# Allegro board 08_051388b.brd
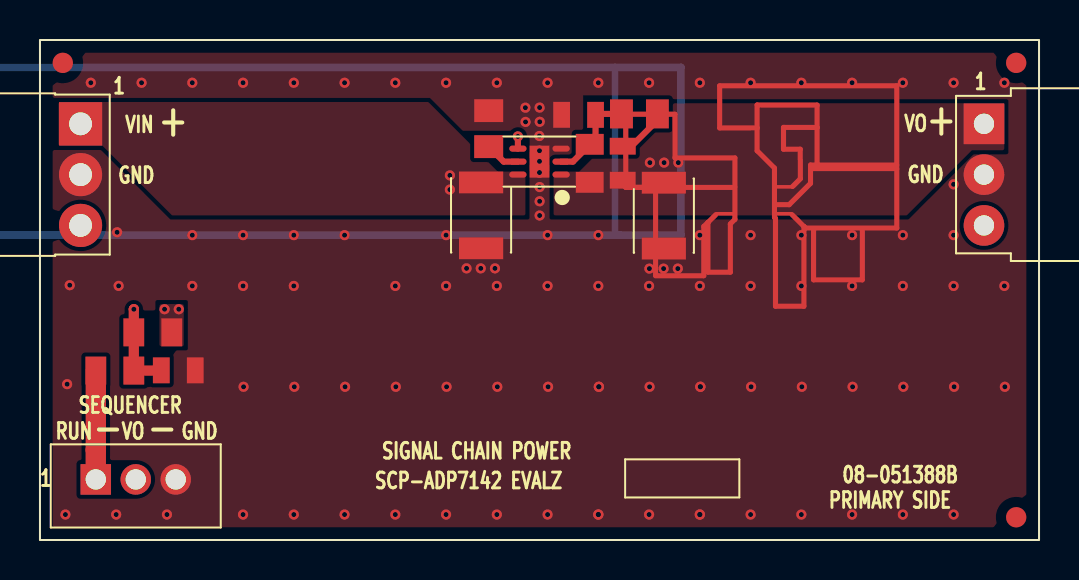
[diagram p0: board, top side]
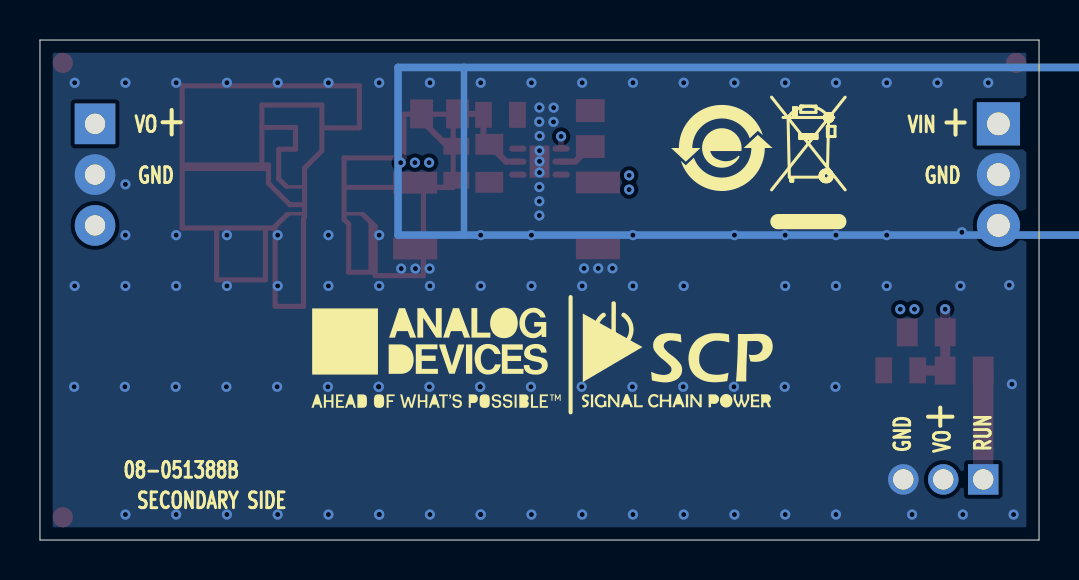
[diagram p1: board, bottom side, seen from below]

Outline 50 x 25 mm; copper layers: TOP, L2_GND, L3_SIG, BOTTOM. Coordinates in mm from the lower left corner of the outline.
Outline path: 0,25 50,25 50,0 0,0 0,25

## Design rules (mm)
constraint set DEFAULT: min track width 0.203

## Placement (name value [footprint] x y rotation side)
C1  2.2uF  [C1210H87]  22.08 16.23 270 top
C2  2.2uF  [C1210H87]  31.22 16.22 270 top
C3  1000PF  [C0805]  22.46 20.57 90 top
C4  0.1uF  [C0805]  30 21.31 180 top
INPUT  PBC03SBAN  [CNTHMHDRRA1X3L300W100H145]  2.03 20.81 270 top
NOREF  -  []  50.02 -0.07 90 top
NOREF#2  -  []  -0.02 25.07 270 top
NOREF#3  -  []  0 25 0 top
NOREF#4  -  []  2.03 20.81 0 top
NOREF#5  -  []  50 0 0 top
NOREF#6  -  []  -36.32 105.77 0 top
NOREF#7  -  []  -19.05 286.11 0 top
NOREF#8  -  [unnamed#2]  48.86 1.14 0 top
NOREF#9  -  []  0 0 0 top
NOREF#10  -  [unnamed#2]  1.14 23.86 0 top
NOREF#11  -  []  -69.98 -54.12 0 top
NOREF#12  -  []  -0.02 -0.07 0 top
NOREF#13  -  [unnamed#2]  48.86 23.86 0 top
NOREF#14  -  []  50 0 90 top
NOREF#15  -  []  50.02 25.07 180 top
NOREF#16  -  []  25.1 39.22 0 top
NOREF#17  -  []  0 0 0 top
NOREF#18  -  []  0 25 0 top
NOREF#19  -  []  92.2 43.03 0 top
NOREF#20  -  []  2.03 20.81 0 top
NOREF#21  -  []  -59.69 348.22 0 top
NOREF#22  -  []  15.88 19.6 180 bottom
NOREF#23  -  []  11.74 15.6 180 bottom
NOREF#24  -  []  30.47 9.07 180 bottom
NOREF#25  -  []  18.07 9.28 180 bottom
OUTPUT  PPPC031LGBN-RC  [CNHDRRA1X3H108]  47.24 20.81 270 top
P1  53253-0370  [CNTHMHDR1X3L315W144H224]  2.79 3.03 0 top
R1  187K  [R0805#2]  27.51 18.83 90 top
R2  10K  [R0805]  26.96 21.26 180 top
R3  1K  [R0805]  29.16 18.84 90 top
R4  1MEG  [R0805#2]  5.64 10.38 180 top
R5  TBD0805  [R0805#2]  3.75 8.47 0 top
R6  TBD0805  [R0805]  6.92 8.48 0 top
U1  ADP7142ACPZN  [DFN6_2X2_PAD1_6X1]  25 18.92 90 top

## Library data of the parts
C1 C2 = CAP: Tolerance: 10; User Part Number: UPN; alternate symbols: (); part number: CAP_SM-2.2UF,100V,10,E015185,C1210H87; tolerance: 10
C3 = CAP: User Part Number: UPN; Tolerance: 10; alternate symbols: (); part number: CAP_SM-1000PF,100V,10,E026082,C0805; tolerance: 10
C4 = CAP: User Part Number: UPN; Tolerance: 5; alternate symbols: (); part number: CAP_SM-0.1UF,50V,5,E015576,C0805; tolerance: 5
INPUT = CN3P: Tolerance: N/A; User Part Number: UPN; alternate symbols: (CNTHMHDRRA1X3L300W100H145_SCP); part number: CN3P_TH-PBC03SBAN,E034137,CNTHMHDRRA1X3L300W100H145; tolerance: N/A
OUTPUT = CN3P: User Part Number: UPN; Tolerance: N/A; alternate symbols: (CNHDRRA1X3H108_SCP); part number: CN3P_TH-PPPC031LGBN-RC,E034111,CNHDRRA1X3H108; tolerance: N/A
P1 = CN3P: Tolerance: N/A; User Part Number: UPN; alternate symbols: (); part number: CN3P_TH-53253-0370,E033940,CNTHMHDR1X3L315W144H224; tolerance: N/A
R1 = RES: User Part Number: UPN; Tolerance: 1; alternate symbols: (R0805L); part number: RES_SM-187K,E015129,1/8W,1,R0805; tolerance: 1
R2 = RES: User Part Number: UPN; Tolerance: 1; alternate symbols: (R0805L); part number: RES_SM-10K,E023450,1/3W,1,R0805; tolerance: 1
R3 = RES: User Part Number: UPN; Tolerance: 1; alternate symbols: (R0805L); part number: RES_SM-1K,E023448,1/3W,1,R0805; tolerance: 1
R4 = RES: User Part Number: UPN; Tolerance: 5; alternate symbols: (); part number: RES_SM-1MEG,E033749,1/8W,5,R0805; tolerance: 5
R5 R6 = RES: User Part Number: UPN; alternate symbols: (R0805L); part number: RES_SM-TBD0805,E004051,TBD0805,TBD0805,R0805
U1 = ADP7142: User Part Number: UPN; Tolerance: N/A; alternate symbols: (); part number: ADP7142_SM-ADP7142ACPZN-R7,E017499,DFN6_2X2_PAD1_6X1; tolerance: N/A

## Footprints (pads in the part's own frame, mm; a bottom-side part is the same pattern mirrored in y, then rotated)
C0805
  rect 1.143x1.448 smd: 1(-0.9,0) 2(0.9,0)
C1210H87
  rect 1.092x2.21 smd: 1(-1.646,0) 2(1.646,0)
CNHDRRA1X3H108
  rect 2.032x2.032 hole 1.016: 1(0,0)
  round 2.032 hole 1.016: 2(2.54,0) 3(5.08,0)
CNTHMHDR1X3L315W144H224
  rect 1.524x1.524 hole 1.016: 1(0,0)
  round 1.524 hole 1.016: 2(2,0) 3(4,0)
CNTHMHDRRA1X3L300W100H145
  rect 2.159x2.159 hole 1.143: 1(0,0)
  round 2.159 hole 1.143: 2(2.54,0) 3(5.08,0)
DFN6_2X2_PAD1_6X1
  oval 0.305x0.864 smd: 1(-0.65,-1.082) 2(0,-1.082) 3(0.65,-1.082) 4(0.65,1.082) 5(0,1.082) 6(-0.65,1.082)
  rect 1.6x0.991 smd: PAD(0,0)
R0805
  rect 0.838x1.295 smd: 1(-0.85,0) 2(0.85,0)
R0805#2
  rect 1.041x1.397 smd: 1(-0.95,0) 2(0.95,0)
unnamed#2
  round 1.016 smd: (0,0)

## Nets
GND: C1.2(N2) C2.2(N2) C3.2(N2) INPUT.2 OUTPUT.2 P1.3(N3) R2.2(N2) R6.2(N2) U1.3 U1.PAD
VIN+: C1.1 INPUT.1 R4.1 U1.6
RUN: P1.1 R5.1
UNNAMED_2_ADP7142_I1_EN: R4.2(N2) R5.2(N2) R6.1 U1.4
UNNAMED_2_ADP7142_I1_SENSE: C4.2(N2) R1.2(N2) R2.1 U1.2
UNNAMED_2_ADP7142_I1_SS: C3.1 U1.5
UNNAMED_2_CAP_I7_N1: C4.1 R3.2(N2)
VO+: C2.1 OUTPUT.1 P1.2 R1.1 R3.1 U1.1(VOUT)

Pads without a net: INPUT 3; OUTPUT 3

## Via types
v1: diameter 0.508, hole 0.254, TOP to BOTTOM, 117 vias

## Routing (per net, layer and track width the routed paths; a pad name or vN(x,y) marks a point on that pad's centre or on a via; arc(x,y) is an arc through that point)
GND: length 0
  vias: v1(1.27,1.27) v1(1.36,7.79) v1(1.49,12.74) v1(2.54,22.86) v1(3.86,15.39) v1(3.81,1.27) v1(3.94,12.71) v1(5.08,22.86) v1(6.35,1.27) v1(7.62,22.86) v1(7.62,15.24) v1(7.62,12.7) v1(10.16,22.86) v1(10.16,15.24) v1(10.16,12.7) v1(10.16,1.27) v1(10.19,7.66) v1(12.7,22.86) v1(12.7,15.24) v1(12.7,12.7) v1(12.73,7.66) v1(12.7,1.27) v1(15.24,22.86) v1(15.24,15.24) v1(15.27,7.66) v1(15.24,1.27) v1(17.78,22.86) v1(17.78,12.7) v1(17.81,7.66) v1(17.78,1.27) v1(20.32,22.86) v1(20.32,15.24) v1(20.32,12.7) v1(20.35,7.66) v1(20.32,1.27) v1(21.35,13.58) v1(22.06,13.58) v1(22.77,13.58) v1(22.86,22.86) v1(22.86,12.7) v1(22.86,1.27) v1(22.89,7.66) v1(24.29,21.62) v1(24.3,20.9) v1(25,21.62) v1(25.01,20.91) v1(24.99,20.2) v1(25,19.47) v1(25,18.93) v1(25,18.37) v1(25.01,17.65) v1(25.01,16.94) v1(25.01,16.22) v1(25.4,22.86) v1(25.4,15.24) v1(25.4,12.7) v1(25.43,7.66) v1(25.4,1.27) v1(27.94,22.86) v1(27.94,15.24) v1(27.94,12.7) v1(27.97,7.66) v1(27.97,7.66) v1(27.94,1.27) v1(27.94,1.27) v1(30.48,22.86) v1(30.5,13.57) v1(30.48,12.7) v1(30.51,7.66) v1(30.48,1.27) v1(31.21,13.57) v1(31.92,13.57) v1(33.02,22.86) v1(33.02,15.24) v1(33.02,12.7) v1(33.05,7.66) v1(33.05,7.66) v1(33.02,1.27) v1(33.02,1.27) v1(35.56,22.86) v1(35.56,15.24) v1(35.56,12.7) v1(35.56,1.27) v1(35.59,7.66) v1(38.1,22.86) v1(38.1,15.24) v1(38.1,12.7) v1(38.13,7.66) v1(38.1,1.27) v1(40.64,22.86) v1(40.64,15.24) v1(40.64,12.7) v1(40.67,7.66) v1(40.64,1.27) v1(43.18,22.86) v1(43.18,15.24) v1(43.18,12.7) v1(43.21,7.66) v1(43.18,1.27) v1(45.72,22.86) v1(45.72,17.78) v1(45.72,15.24) v1(45.72,12.7) v1(45.75,7.66) v1(45.72,1.27) v1(48.26,22.86) v1(48.26,12.7) v1(48.29,7.66)
VIN+: length 17.5
  L3_SIG w0.508: v1(20.51,18.23) v1(20.51,17.52) 14.53,11.54 v1(6.95,11.54) v1(6.24,11.54)
RUN: length 5.4
  TOP w1.016: R5.1 2.8,4.5 2.79,4.5 P1.1
UNNAMED_2_ADP7142_I1_EN: length 29.3
  TOP w0.305: U1.4 v1(23.92,20.18)
  TOP w0.508: R6.1 6.06,8.47 R5.2 4.7,10.38 R4.2 4.69,11.53 v1(4.7,11.54)
  L3_SIG w0.508: v1(23.92,20.18) 10.8,20.18 4.7,14.08 v1(4.7,11.54)
UNNAMED_2_ADP7142_I1_SENSE: length 4.7
  TOP w0.305: C4.2 27.85,21.31 R2.1 27.81,20.08 R1.2 27.51,19.76 26.67,18.92 U1.2
UNNAMED_2_ADP7142_I1_SS: length 1.8
  TOP w0.305: C3.1 23.21,18.92 U1.5
UNNAMED_2_CAP_I7_N1: length 2.6
  TOP w0.305: R3.2 29.6,19.69 30.9,20.99 C4.1
VO+: length 34.5
  L3_SIG w0.508: v1(31.95,18.87) v1(31.24,18.87) v1(30.52,18.87) 20.46,8.81 9.28,8.81 4.79,4.32 P1.2

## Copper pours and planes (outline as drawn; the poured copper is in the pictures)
GND on TOP: 0.64,0.64 0.64,24.36 49.36,24.36 49.36,0.64 ; 5 cut-outs
GND on BOTTOM, L2_GND, L3_SIG: 0.64,0.64 0.64,24.36 49.36,24.36 49.36,0.64
VIN+ on TOP: 24.3,18.42 24.3,16.23 6.61,16.23 3.14,19.7 0.93,19.7 0.93,21.9 19.43,21.9 22.91,18.42
VIN+ on TOP: 5.98,9.68 5.98,11.79 7.2,11.79 7.2,9.68
VO+ on TOP: 25.7,16.23 25.7,18.42 26.99,18.42 27.63,19.07 29.81,19.07 29.81,20.3 28.87,20.3 30.4,21.84 48.26,21.84 48.26,19.49 46.64,19.49 43.38,16.23

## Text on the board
Ref Des/Silkscreen Bottom: GND | VIN | SECONDARY SIDE | 08-051388B | VO | RUN | +
Ref Des/Silkscreen Top: RUN | SEQUENCER | VO | GND | VIN | SCP-ADP7142 EVALZ | SIGNAL CHAIN POWER | PRIMARY SIDE | 08-051388B | - | +
PAGE_OUTLINE: 04DEC18 | B | AS PER ECR-086419 | 07MAY19 | J.VIERNES
DIMENSION: (REF) | SEE FAB NOTES 15 | DIA MAX
User.11: VIEW FROM PRIMARY SIDE
User.15: 15.    THRU VIAS TO BE FILLED WITH SOLDERMASK. | .0028" | .0014" | .0035"
User.17: L2 GND | 08-      -07
User.18: L3 SIG | 08-      -08
User.45: FIGURE | SIZE | 10.0 | 40.0 | 45.0 | PLATED | FINISHED HOLES IN MILS | ALL UNITS ARE IN MILS | QTY | 117 | 6 | 3 | TOLERANCE/NOTES
